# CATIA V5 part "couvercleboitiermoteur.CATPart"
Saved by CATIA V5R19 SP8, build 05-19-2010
Part number: couvercleboitiermoteur
Revision: ANY
Definition: UNKNOWN
Nomenclature: couvercleboitiermoteur
Source: Unknown
Bounding box of the stored display mesh (mm): x 119.466 to 156.534, y 7 to 36, z 0 to 6.5
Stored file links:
  D:\Documents\1_Travail\1 - ac-limoges.fr\ac-limoges.fr\Emmanuel Maynard - STI2D_Turgot\2 -2I2D\2_SEQUENCE_Serrure_Biométrique\5-Spé_ITEC\Serrure_Bio_Eleve\couvercleboitiermoteur.CATPart
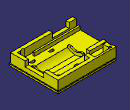
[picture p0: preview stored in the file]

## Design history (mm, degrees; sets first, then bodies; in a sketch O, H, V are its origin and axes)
Body1 "Enlèv. mat.-Extru.12" (main body)
  Solid1: solid without history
